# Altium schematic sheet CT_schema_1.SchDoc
size 456 x 258 mm
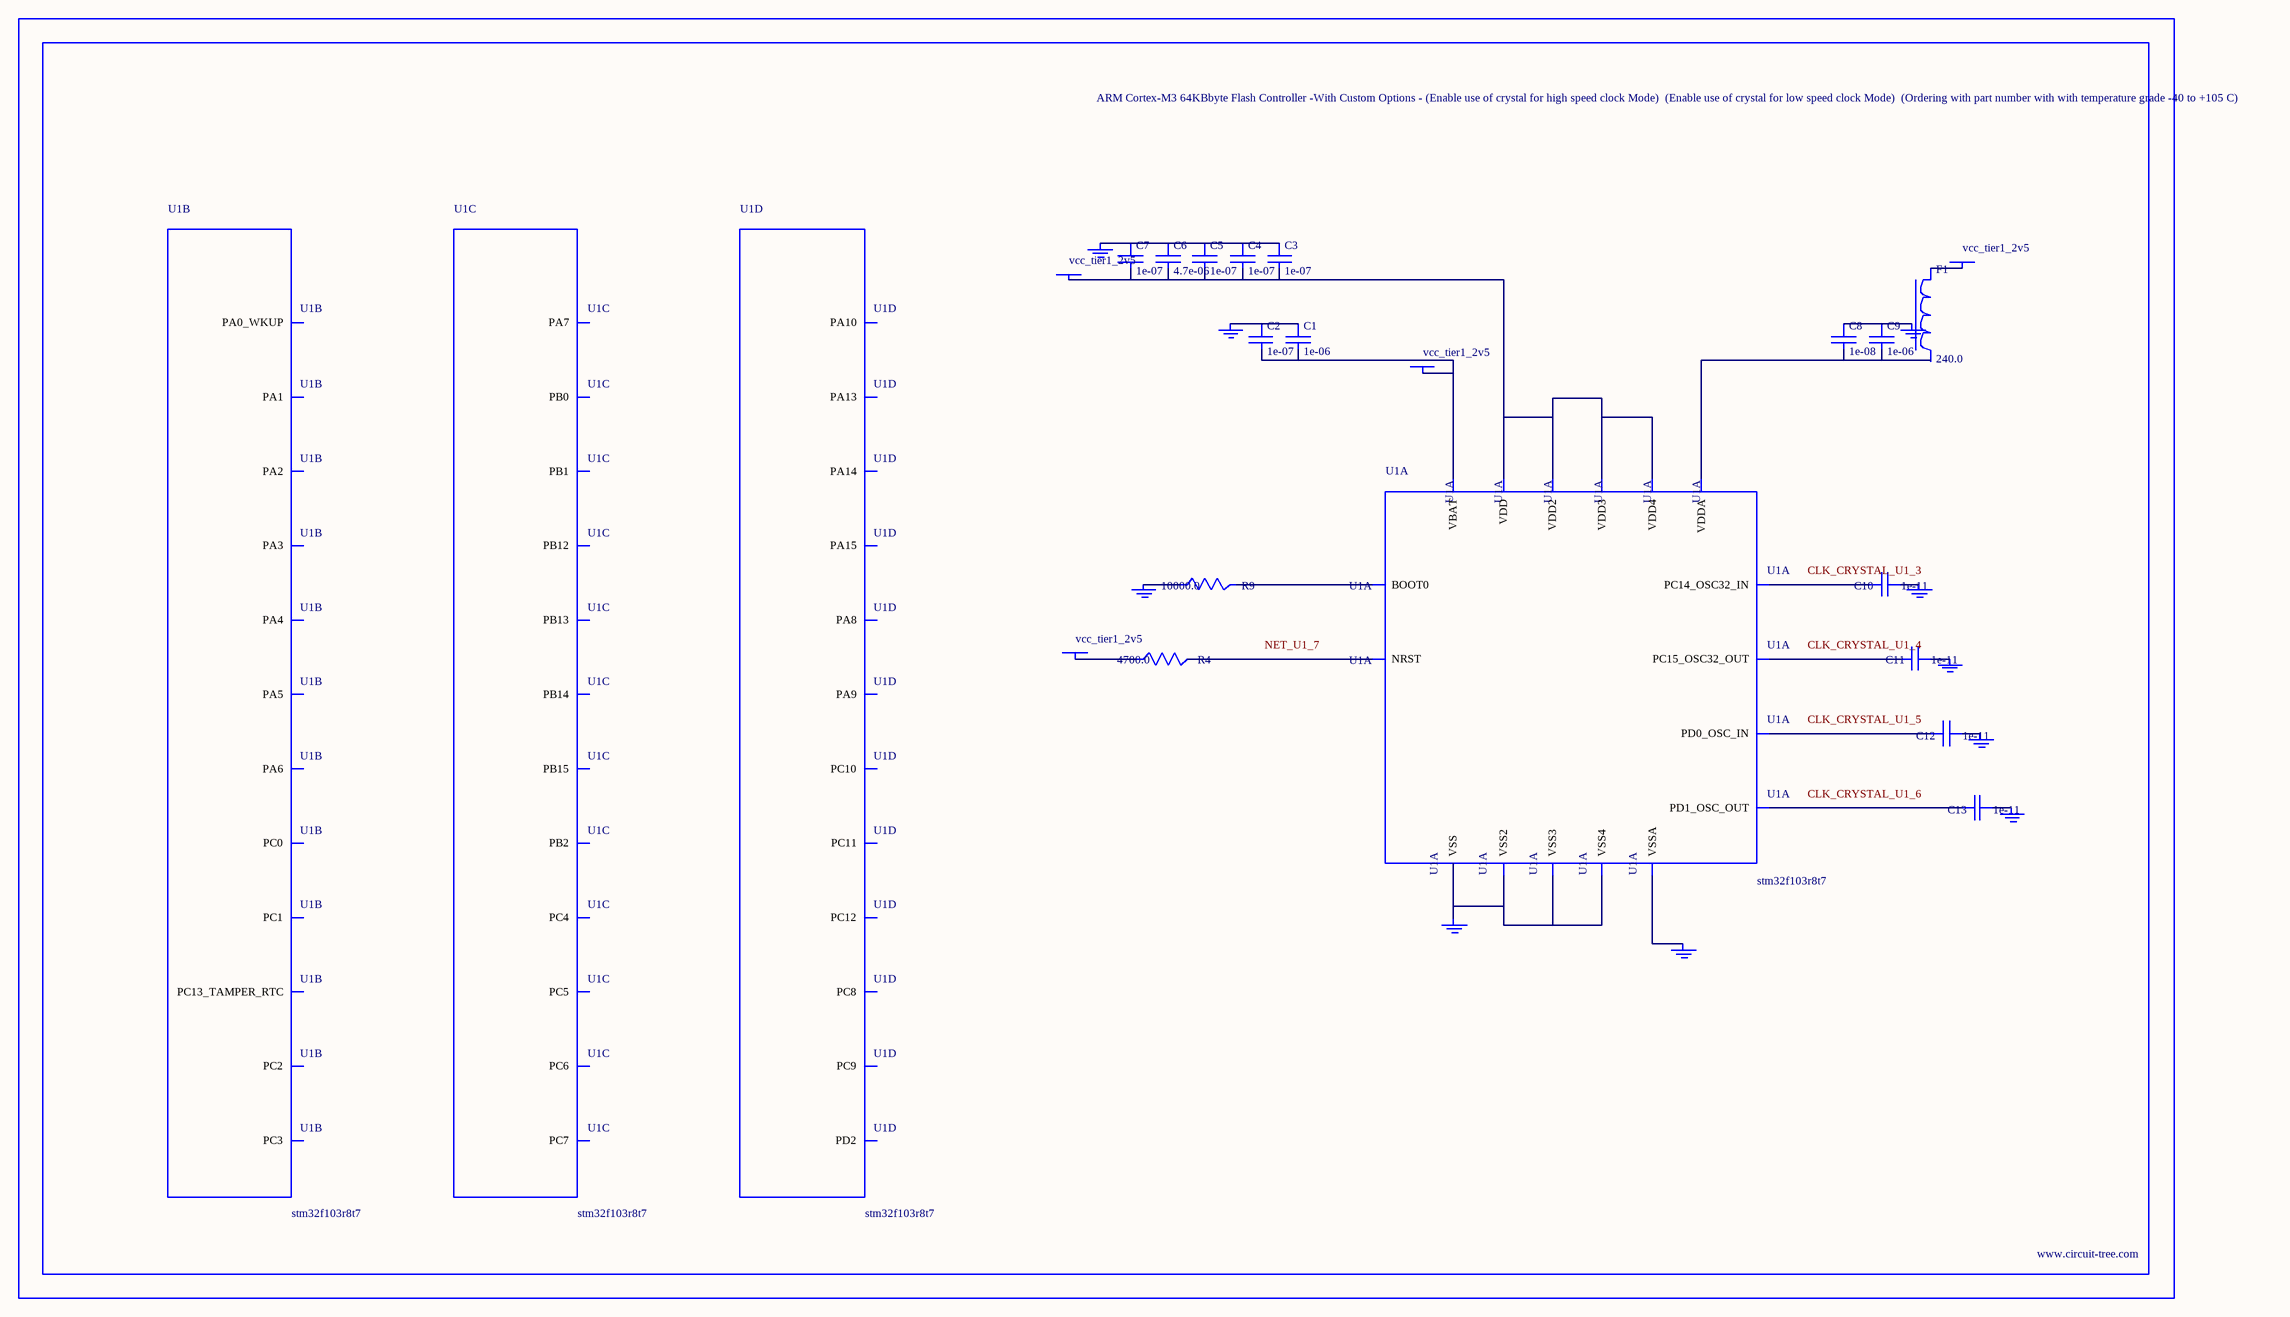
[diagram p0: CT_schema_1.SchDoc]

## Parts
BORDER0  (no value)
C1  1e-06  [C0603]
C2  1e-07  [C0603]
C3  1e-07  [C0603]
C4  1e-07  [C0603]
C5  1e-07  [C0603]
C6  4.7e-06  [C0603]
C7  1e-07  [C0603]
C8  1e-08  [C0603]
C9  1e-06  [C0603]
C10  1e-11  [C0402]
C11  1e-11  [C0402]
C12  1e-11  [C0402]
C13  1e-11  [C0402]
F1  240.0  [L0603]
GND_INSTANCE_0_0  (no value)
GND_INSTANCE_0_1  (no value)
GND_INSTANCE_0_2  (no value)
GND_INSTANCE_0_3  (no value)
GND_INSTANCE_0_4  (no value)
GND_INSTANCE_0_5  (no value)
GND_INSTANCE_0_6  (no value)
GND_INSTANCE_0_7  (no value)
GND_INSTANCE_0_8  (no value)
GND_INSTANCE_0_9  (no value)
POWER_INSTANCE_0_0  vcc_tier1_2v5
POWER_INSTANCE_0_1  vcc_tier1_2v5
POWER_INSTANCE_0_2  vcc_tier1_2v5
POWER_INSTANCE_0_3  vcc_tier1_2v5
R4  4700.0  [R0603]
R9  10000.0  [R0603]
U1  stm32f103r8t7  [LQFP64]  (parts A,B,C,D of 8)

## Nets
NetC1_1: C1.1 C2.1 GND_INSTANCE_0_0.0(GND)
NetC1_2: C1.2 C2.2 POWER_INSTANCE_0_0.0(PWR) U1.1(VBAT)
NetC3_1: C3.1 C4.1 C5.1 C6.1 C7.1 GND_INSTANCE_0_7.0(GND)
NetC3_2: C3.2 C4.2 C5.2 C6.2 C7.2 POWER_INSTANCE_0_2.0(PWR) U1.19(VDD) U1.32(VDD2) U1.48(VDD3) U1.64(VDD4)
NetC8_1: C8.1 C9.1 GND_INSTANCE_0_6.0(GND)
NetC8_2: C8.2 C9.2 U1.13(VDDA)
NetC10_1: C10.1 GND_INSTANCE_0_1.0(GND)
NetC10_2: C10.2 U1.3(PC14_OSC32_IN)
NetC11_1: C11.1 GND_INSTANCE_0_2.0(GND)
NetC11_2: C11.2 U1.4(PC15_OSC32_OUT)
NetC12_1: C12.1 GND_INSTANCE_0_3.0(GND)
NetC12_2: C12.2 U1.5(PD0_OSC_IN)
NetC13_1: C13.1 GND_INSTANCE_0_4.0(GND)
NetC13_2: C13.2 U1.6(PD1_OSC_OUT)
NetF1_1: F1.1 POWER_INSTANCE_0_1.0(PWR)
NetGND_INSTANCE_0_5_0: GND_INSTANCE_0_5.0(GND) U1.12(VSSA)
NetGND_INSTANCE_0_8_0: GND_INSTANCE_0_8.0(GND) R9.1
NetGND_INSTANCE_0_9_0: GND_INSTANCE_0_9.0(GND) U1.18(VSS) U1.31(VSS2) U1.47(VSS3) U1.63(VSS4)
NetPOWER_INSTANCE_0_3_0: POWER_INSTANCE_0_3.0(PWR) R4.1
NetR4_2: R4.2 U1.7(NRST)
NetR9_2: R9.2 U1.60(BOOT0)

Not connected (* = marked no-connect by the designer): F1 2; U1 2(PC13_TAMPER_RTC) 8(PC0) 9(PC1) 10(PC2) 11(PC3) 14(PA0_WKUP) 15(PA1) 16(PA2) 17(PA3) 20(PA4) 21(PA5) 22(PA6) 23(PA7) 24(PC4) 25(PC5) 26(PB0) 27(PB1) 28(PB2) 33(PB12) 34(PB13) 35(PB14) 36(PB15) 37(PC6) 38(PC7) 39(PC8) 40(PC9) 41(PA8) 42(PA9) 43(PA10) 46(PA13) 49(PA14) 50(PA15) 51(PC10) 52(PC11) 53(PC12) 54(PD2)

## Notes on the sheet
- Labels drawn without touching a wire or pin: CLK_CRYSTAL_U1_3, CLK_CRYSTAL_U1_4, CLK_CRYSTAL_U1_5, CLK_CRYSTAL_U1_6, NET_U1_7

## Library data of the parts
BORDER0 = BORDER_PAGE0
C1 C9 = C0603C105K3RACTU
C2-C5 C7 = 06035C104K4Z2A
C6 = GRM188R6YA475KE15D
C8 = 06035C103K4Z2A
C10-C13 = C0402C100K3GACTU
F1 = Z0603C241ASMST
GND_INSTANCE_0_0-GND_INSTANCE_0_9 = GND
POWER_INSTANCE_0_0-POWER_INSTANCE_0_3 = PWR
R4 = RC0603JR-074K7L
R9 = RC0603JR-0710KL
